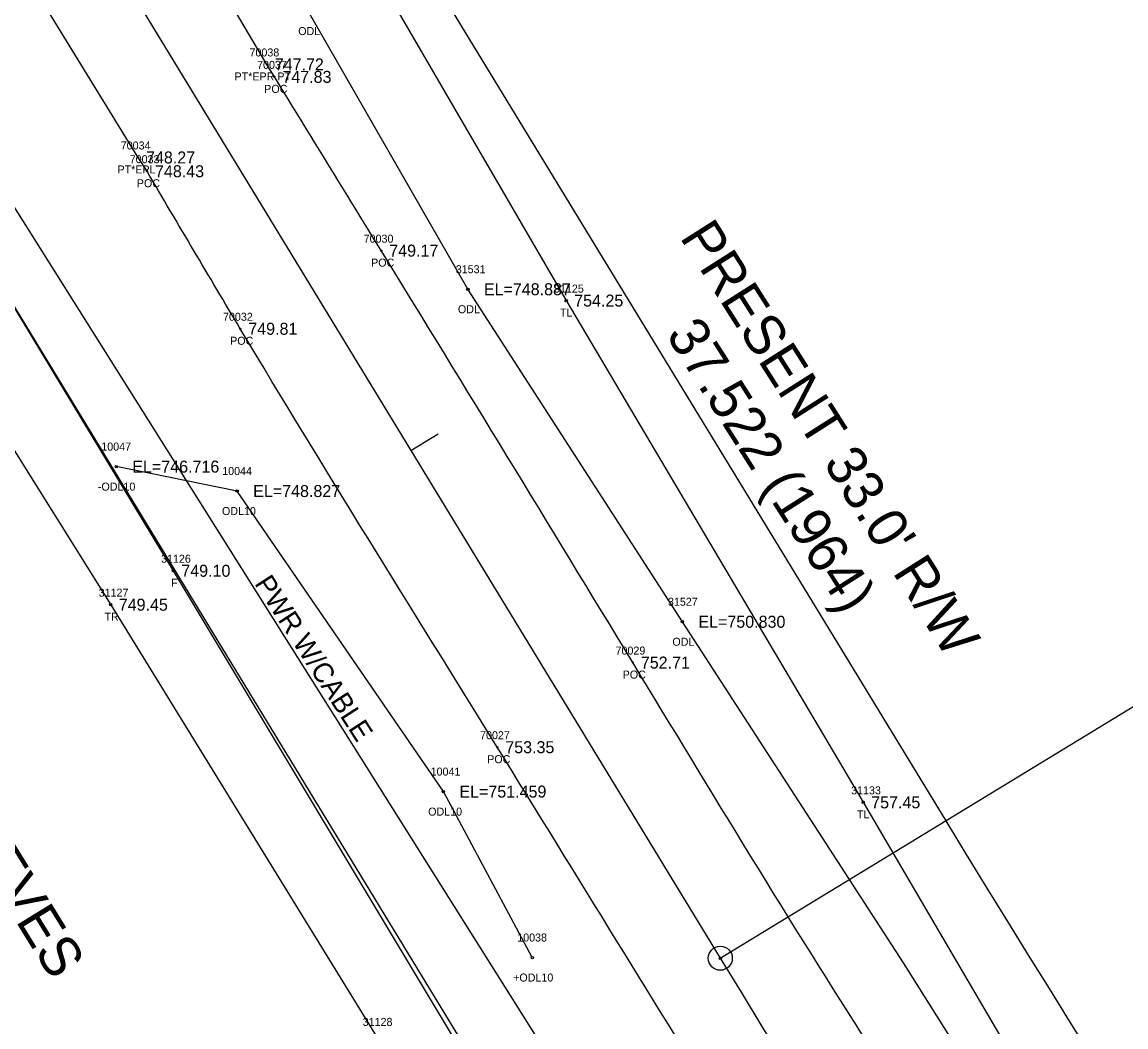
# Model space of a CAD drawing. Extents: x 1375131 to 1378678, y 999028 to 1004053.
# Drawn here: x 1377868.1 to 1378006.1, y 1000681.6 to 1000807.1 of the extents above; entities that cross this region are included whole.
import ezdxf

# ---------------------------------------------------------------- set-up
doc = ezdxf.new("R2010")
doc.units = 0
for name, color, linetype in [('RD_EX_DV_TX_Prop(Owner ID)', 7, 'Continuous'), ('RD_EX_Fence_Other', 7, 'Continuous'), ('RD_EX_Fence_Other_txCode', 7, 'Continuous'), ('RD_EX_H2O', 7, 'Continuous'), ('RD_EX_H2O_txCode', 7, 'Continuous'), ('RD_EX_Road', 7, 'Continuous'), ('RD_EX_Road_txCode', 7, 'Continuous'), ('RD_EX_RW', 7, 'Continuous'), ('RD_EX_RW_TX', 7, 'Continuous'), ('RD_EX_SU_Elec', 7, 'Continuous'), ('RD_EX_TX_Fence_Other_ELEV', 7, 'Continuous'), ('RD_EX_TX_H2O_ELEV', 7, 'Continuous'), ('RD_EX_TX_Road_ELEV', 7, 'Continuous'), ('RD_EX_TX_VEG_ELEV', 7, 'Continuous'), ('RD_EX_VEG', 7, 'Continuous'), ('RD_EX_VEG_txCode', 7, 'Continuous'), ('RD_HC_Cl', 7, 'Continuous'), ('RD_HC_Data', 7, 'Continuous'), ('RD_HC_Data_Tic', 7, 'Continuous'), ('RD_SMD_Locator', 7, 'Continuous'), ('RD_TX_Utilities', 7, 'Continuous')]:
    doc.layers.add(name, color=color, linetype=linetype)

msp = doc.modelspace()

# ---------------------------------------------------------------- linework, layer by layer
at = {"layer": 'RD_EX_Fence_Other'}
msp.add_lwpolyline([(1377790.17, 1000897.18), (1377827.38, 1000835.92), (1377853.95, 1000793.25), (1377887.04, 1000738.59), (1377922.52, 1000679.45)], dxfattribs=at)
at = {"layer": 'RD_EX_H2O'}
for points in [[(1378004.9, 1000647.31), (1377978.29, 1000689.62), (1377950.66, 1000732.22), (1377923.85, 1000773.76), (1377903.9, 1000808.51), (1377896.3, 1000821.1)], [(1377931.9, 1000690.27), (1377920.79, 1000711), (1377895.02, 1000748.55), (1377879.91, 1000751.6)]]:
    msp.add_lwpolyline(points, dxfattribs=at)
at = {"layer": 'RD_EX_Road'}
for points in [[(1377899.67, 1000800.29), (1377898.72, 1000801.84), (1377870.31, 1000849.94), (1377847.28, 1000887.89), (1377815.15, 1000940.58), (1377781.51, 1000995.26), (1377748.62, 1001049.21), (1377716.58, 1001099.53), (1377686.67, 1001148.78), (1377656.47, 1001199.11), (1377629.54, 1001244.18), (1377599.89, 1001292.67), (1377570.87, 1001341.43), (1377539.83, 1001392.47), (1377511.01, 1001440.31), (1377480.72, 1001490), (1377449.73, 1001541.49), (1377420.9, 1001591.95), (1377390.45, 1001644.41)], [(1377883.75, 1000788.5), (1377882.63, 1000790.22), (1377852.26, 1000839.6), (1377828.46, 1000879.31), (1377797, 1000930.66), (1377763.07, 1000986.65), (1377731.87, 1001037.81), (1377700.31, 1001089.98), (1377670.43, 1001138.24), (1377639.73, 1001190.03), (1377611.89, 1001234.23), (1377582.78, 1001282.57), (1377552.22, 1001331.03), (1377522.24, 1001382.35), (1377494.26, 1001430.19), (1377463.17, 1001481.14), (1377433.42, 1001531.29), (1377403.14, 1001580.98), (1377371.36, 1001632.19)]]:
    msp.add_lwpolyline(points, dxfattribs=at)
for points in [[(1378177.15, 1000392.85), (1378139.73, 1000441.52), (1378104.67, 1000487.69), (1378071.79, 1000533.09), (1378038.45, 1000579.8), (1378007.55, 1000627.96), (1377974.27, 1000678.86), (1377944.47, 1000727.12), (1377913.03, 1000778.58), (1377899.67, 1000800.29)], [(1378161.36, 1000381.16), (1378123.91, 1000428.54), (1378087.58, 1000476.32), (1378055.08, 1000520.94), (1378021.67, 1000568.71), (1377989.95, 1000617.08), (1377957.33, 1000668.38), (1377927.53, 1000716.55), (1377895.41, 1000768.82), (1377883.75, 1000788.5)]]:
    msp.add_spline(points, degree=3, dxfattribs=at)
at = {"layer": 'RD_EX_RW'}
for p, q in [((1377592.75, 1001348.44), (1377983.57, 1000707.36)), ((1377536.4, 1001314.08), (1377927.22, 1000673.01))]:
    msp.add_line(p, q, dxfattribs=at)
msp.add_arc((1380260.77, 1002095.62), 2667, 211.36799, 218.13892, dxfattribs=at)
at = {"layer": 'RD_EX_SU_Elec'}
msp.add_lwpolyline([(1377798.03, 1000893.79), (1378025.9, 1000531.77), (1378278.5, 1000217.55)], dxfattribs=at)
at = {"layer": 'RD_EX_VEG'}
for points in [[(1377698.52, 1000917.3), (1377753.14, 1000944.68), (1377782.86, 1000890.37), (1377819.02, 1000831), (1377844.41, 1000789.91), (1377879.22, 1000734.35), (1377912.22, 1000680.73), (1377954.28, 1000611.32), (1377992.95, 1000554.02), (1378022.09, 1000512.01), (1378056.34, 1000459.65), (1378089.87, 1000422.45), (1378122.09, 1000390.03), (1378125.27, 1000369.76), (1378093.99, 1000348.6)], [(1377975.86, 1000867.47), (1377940.96, 1000846.12), (1377905.66, 1000824.77), (1377936.14, 1000772.34), (1377973.26, 1000709.66), (1378011.8, 1000643.94), (1378051.79, 1000581.32), (1378077.27, 1000544.45), (1378109.04, 1000498.32), (1378149.58, 1000443.93), (1378185.36, 1000398.58)]]:
    msp.add_lwpolyline(points, dxfattribs=at)
at = {"layer": 'RD_HC_Cl'}
msp.add_line((1377564.57, 1001331.26), (1377955.4, 1000690.18), dxfattribs=at)
msp.add_arc((1380260.77, 1002095.62), 2700, 211.36799, 218.13892, dxfattribs=at)
at = {"layer": 'RD_HC_Data'}
msp.add_line((1377955.4, 1000690.18), (1378055.24, 1000751.05), dxfattribs=at)
for radius in [1.5, 0.141]:
    msp.add_circle((1377955.4, 1000690.18), radius, dxfattribs=at)
at = {"layer": 'RD_HC_Data_Tic'}
msp.add_line((1377916.74, 1000753.6), (1377920.15, 1000755.68), dxfattribs=at)
at = {"layer": 'RD_SMD_Locator'}
for centre, radius in [((1377898.72, 1000801.84), 0.075), ((1377899.67, 1000800.29), 0.075), ((1377882.63, 1000790.22), 0.075), ((1377883.75, 1000788.5), 0.075), ((1377913.03, 1000778.58), 0.075), ((1377923.85, 1000773.76), 0.15), ((1377936.14, 1000772.34), 0.15), ((1377895.41, 1000768.82), 0.075), ((1377879.91, 1000751.6), 0.15), ((1377895.02, 1000748.55), 0.15), ((1377887.04, 1000738.59), 0.15), ((1377879.22, 1000734.35), 0.15), ((1377950.66, 1000732.22), 0.15), ((1377944.47, 1000727.12), 0.075), ((1377927.53, 1000716.55), 0.075), ((1377920.79, 1000711), 0.15), ((1377973.26, 1000709.66), 0.15), ((1377931.9, 1000690.27), 0.15)]:
    msp.add_circle(centre, radius, dxfattribs=at)

# ---------------------------------------------------------------- texts
at = {"layer": 'RD_EX_DV_TX_Prop(Owner ID)'}
msp.add_text('JARED DAVID & ALLIE MARIE REEVES', height=5, rotation=301.5778, dxfattribs=at).set_placement((1377807.73, 1000791.73))
at = {"layer": 'RD_EX_Fence_Other_txCode'}
for s, p in [('31126', (1377885.51, 1000739.59)), ('F', (1377886.76, 1000736.59))]:
    msp.add_text(s, height=1, dxfattribs=at).set_placement(p)
at = {"layer": 'RD_EX_H2O_txCode'}
for s, p in [('ODL', (1377902.65, 1000805.51)), ('31531', (1377922.34, 1000775.76)), ('ODL', (1377922.61, 1000770.76)), ('10047', (1377878.04, 1000753.6)), ('10044', (1377893.15, 1000750.55)), ('-ODL10', (1377877.61, 1000748.6)), ('ODL10', (1377893.12, 1000745.55)), ('31527', (1377948.86, 1000734.22)), ('ODL', (1377949.41, 1000729.22)), ('10041', (1377919.2, 1000713)), ('ODL10', (1377918.89, 1000708)), ('10038', (1377930.02, 1000692.27)), ('+ODL10', (1377929.51, 1000687.27))]:
    msp.add_text(s, height=1, dxfattribs=at).set_placement(p)
at = {"layer": 'RD_EX_Road_txCode'}
for s, p in [('70038', (1377896.56, 1000802.84)), ('70037', (1377897.51, 1000801.29)), ('PT*EPR PT', (1377894.69, 1000799.84)), ('POC', (1377898.4, 1000798.29)), ('70034', (1377880.47, 1000791.22)), ('70033', (1377881.59, 1000789.5)), ('PT*EPL', (1377880.06, 1000788.22)), ('POC', (1377882.48, 1000786.5)), ('70030', (1377910.83, 1000779.58)), ('POC', (1377911.76, 1000776.58)), ('70032', (1377893.25, 1000769.82)), ('POC', (1377894.14, 1000766.82)), ('70029', (1377942.31, 1000728.12)), ('POC', (1377943.2, 1000725.12)), ('70027', (1377925.38, 1000717.55)), ('POC', (1377926.27, 1000714.55))]:
    msp.add_text(s, height=1, dxfattribs=at).set_placement(p)
at = {"layer": 'RD_EX_RW_TX'}
for s, p in [("PRESENT 33.0' R/W", (1377950.26, 1000780.27)), ('37.522 (1964)', (1377948.53, 1000768.08))]:
    msp.add_text(s, height=5, rotation=302.4308, dxfattribs=at).set_placement(p)
at = {"layer": 'RD_EX_TX_Fence_Other_ELEV'}
msp.add_text('749.10', height=1.5, dxfattribs=at).set_placement((1377888.04, 1000737.84))
at = {"layer": 'RD_EX_TX_H2O_ELEV'}
for s, p in [('EL=748.887', (1377925.85, 1000773.01)), ('EL=746.716', (1377881.91, 1000750.85)), ('EL=748.827', (1377897.02, 1000747.8)), ('EL=750.830', (1377952.66, 1000731.47)), ('EL=751.459', (1377922.79, 1000710.25))]:
    msp.add_text(s, height=1.5, dxfattribs=at).set_placement(p)
at = {"layer": 'RD_EX_TX_Road_ELEV'}
for s, p in [('747.72', (1377899.72, 1000801.09)), ('747.83', (1377900.67, 1000799.54)), ('748.27', (1377883.63, 1000789.47)), ('748.43', (1377884.75, 1000787.75)), ('749.17', (1377914.03, 1000777.83)), ('749.81', (1377896.41, 1000768.07)), ('752.71', (1377945.47, 1000726.37)), ('753.35', (1377928.53, 1000715.8))]:
    msp.add_text(s, height=1.5, dxfattribs=at).set_placement(p)
at = {"layer": 'RD_EX_TX_VEG_ELEV'}
for s, p in [('754.25', (1377937.14, 1000771.59)), ('749.45', (1377880.22, 1000733.6)), ('757.45', (1377974.26, 1000708.91))]:
    msp.add_text(s, height=1.5, dxfattribs=at).set_placement(p)
at = {"layer": 'RD_EX_VEG_txCode'}
for s, p in [('31125', (1377934.62, 1000773.34)), ('TL', (1377935.36, 1000770.34)), ('31127', (1377877.71, 1000735.35)), ('TR', (1377878.43, 1000732.35)), ('31133', (1377971.75, 1000710.66)), ('TL', (1377972.49, 1000707.66)), ('31128', (1377910.71, 1000681.73))]:
    msp.add_text(s, height=1, dxfattribs=at).set_placement(p)
at = {"layer": 'RD_TX_Utilities'}
msp.add_text('PWR W/CABLE', height=2.5, rotation=302.8744, dxfattribs=at).set_placement((1377897.12, 1000737))

doc.saveas('drawing.dxf')
